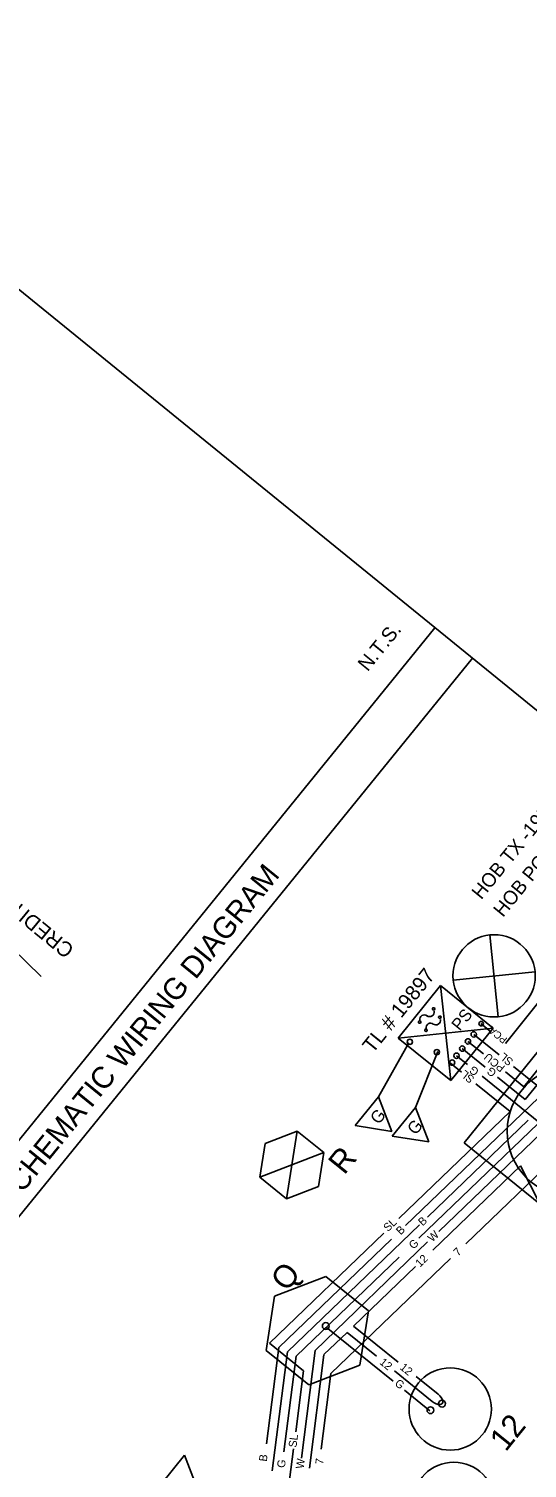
# Model space of a CAD drawing. Extents: x 592613 to 600223, y 4837996 to 4840103.
# Drawn here: x 592974.5 to 592995.2, y 4839219.9 to 4839279.7 of the extents above; entities that cross this region are included whole.
import ezdxf

# ---------------------------------------------------------------- set-up
doc = ezdxf.new("R2010")
doc.units = 0
for name, color, linetype in [('ENG_BORDER', 7, 'Continuous'), ('ENG_TITLEBLOCK', 7, 'Continuous'), ('ENG_TX_TITLEBLOCK', 7, 'Continuous'), ('Level 32', 7, 'Continuous'), ('Level 57', 7, 'Continuous'), ('ROW_ENG_ROW', 7, 'Continuous'), ('TCS_ELEC-CHAMBER-NEW', 7, 'Continuous'), ('TCS_FUSE', 7, 'Continuous'), ('TCS_HYDROSUPPLY', 7, 'Continuous'), ('TCS_PLATE', 7, 'Continuous'), ('TCS_POLE-EXIST', 7, 'Continuous'), ('TCS_POLE-NEW', 7, 'Continuous'), ('TCS_POWER', 7, 'Continuous'), ('TCS_WR_12', 7, 'Continuous'), ('TCS_WR_7', 7, 'Continuous'), ('TCS_WR_B', 7, 'Continuous'), ('TCS_WR_G', 7, 'Continuous'), ('TCS_WR_PCA', 7, 'Continuous'), ('TCS_WR_PCU', 7, 'Continuous'), ('TCS_WR_SL', 7, 'Continuous'), ('TCS_WR_W', 7, 'Continuous')]:
    doc.layers.add(name, color=color, linetype=linetype)

msp = doc.modelspace()

# ---------------------------------------------------------------- linework, layer by layer
at = {"layer": 'ENG_BORDER'}
msp.add_line((593034.225, 4839220.017), (592929.842, 4839304.827), dxfattribs=at)
at = {"layer": 'ENG_TITLEBLOCK'}
for p, q in [((592963.831, 4839220.942), (592991.37, 4839254.837)), ((592965.387, 4839219.678), (592992.927, 4839253.572))]:
    msp.add_line(p, q, dxfattribs=at)
at = {"layer": 'Level 57'}
msp.add_circle((592993.289, 4839238.384), 0.095, dxfattribs=at)
at = {"layer": 'ROW_ENG_ROW'}
msp.add_line((592974.997, 4839240.339), (592971.811, 4839243.434), dxfattribs=at)
at = {"layer": 'TCS_ELEC-CHAMBER-NEW'}
for p, q in [((592996.605, 4839238.421), (592992.576, 4839233.433)), ((592984.315, 4839233.409), (592985.645, 4839233.921)), ((592985.645, 4839233.921), (592985.203, 4839231.106)), ((592985.645, 4839233.921), (592986.753, 4839233.026)), ((592984.094, 4839232.001), (592984.315, 4839233.409)), ((592992.576, 4839233.433), (592997.564, 4839229.404)), ((592984.094, 4839232.001), (592986.753, 4839233.026)), ((592986.753, 4839233.026), (592986.532, 4839231.618)), ((592985.203, 4839231.106), (592984.094, 4839232.001)), ((592986.532, 4839231.618), (592985.203, 4839231.106)), ((592984.702, 4839227.06), (592986.829, 4839227.88)), ((592986.829, 4839227.88), (592988.603, 4839226.448)), ((592984.348, 4839224.808), (592984.702, 4839227.06)), ((592988.603, 4839226.448), (592988.249, 4839224.195)), ((592986.122, 4839223.375), (592984.348, 4839224.808)), ((592988.249, 4839224.195), (592986.122, 4839223.375))]:
    msp.add_line(p, q, dxfattribs=at)
msp.add_circle((592997.085, 4839233.914), 2.715, dxfattribs=at)
at = {"layer": 'TCS_FUSE'}
for centre, radius, start, end in [((592990.926, 4839238.562), 0.189, 53.79169, 190.44043), ((592991.149, 4839238.866), 0.189, 233.79169, 10.44043), ((592991.311, 4839238.998), 0.0513, 51.07435, 231.07435), ((592991.311, 4839238.998), 0.0513, 231.07435, 51.07435), ((592991.408, 4839238.524), 0.189, 233.79169, 10.44043), ((592991.57, 4839238.655), 0.0513, 51.07435, 231.07435), ((592991.57, 4839238.655), 0.0513, 231.07435, 51.07435), ((592990.735, 4839238.451), 0.0513, 51.07435, 231.07435), ((592990.735, 4839238.451), 0.0513, 231.07435, 51.07435), ((592990.994, 4839238.109), 0.0513, 51.07435, 231.07435), ((592990.994, 4839238.109), 0.0513, 231.07435, 51.07435), ((592991.185, 4839238.219), 0.189, 53.79169, 190.44043)]:
    msp.add_arc(centre, radius, start, end, dxfattribs=at)
at = {"layer": 'TCS_PLATE'}
for p, q in [((592989.015, 4839235.345), (592988.048, 4839234.148)), ((592989.569, 4839233.909), (592989.015, 4839235.345)), ((592990.556, 4839234.905), (592989.589, 4839233.709)), ((592991.109, 4839233.47), (592990.556, 4839234.905)), ((592988.048, 4839234.148), (592989.569, 4839233.909)), ((592989.589, 4839233.709), (592991.109, 4839233.47)), ((592980.957, 4839220.448), (592979.99, 4839219.252)), ((592981.511, 4839219.013), (592980.957, 4839220.448))]:
    msp.add_line(p, q, dxfattribs=at)
at = {"layer": 'TCS_POLE-EXIST'}
for p, q in [((592994.001, 4839238.672), (592993.656, 4839242.074)), ((592995.529, 4839240.546), (592992.127, 4839240.2))]:
    msp.add_line(p, q, dxfattribs=at)
msp.add_circle((592993.828, 4839240.374), 1.71, dxfattribs=at)
at = {"layer": 'TCS_POLE-NEW'}
for centre in [(592992.003, 4839222.372), (592992.152, 4839218.453)]:
    msp.add_circle(centre, 1.71, dxfattribs=at)
at = {"layer": 'TCS_POWER'}
for p, q in [((592991.604, 4839239.965), (592989.841, 4839237.784)), ((592992.022, 4839236.021), (592991.604, 4839239.965)), ((592993.785, 4839238.202), (592991.604, 4839239.965)), ((592989.841, 4839237.784), (592993.785, 4839238.202)), ((592992.022, 4839236.021), (592993.785, 4839238.202)), ((592989.841, 4839237.784), (592992.022, 4839236.021))]:
    msp.add_line(p, q, dxfattribs=at)
at = {"layer": 'TCS_WR_12'}
for p, q in [((592994.926, 4839232.484), (592991.275, 4839228.976)), ((592996.111, 4839230.135), (592994.926, 4839232.484)), ((592990.563, 4839228.292), (592987.986, 4839225.815)), ((592987.713, 4839225.553), (592986.755, 4839224.632)), ((592987.713, 4839225.553), (592988.938, 4839224.563)), ((592987.989, 4839225.818), (592989.845, 4839224.319)), ((592986.754, 4839224.625), (592986.154, 4839219.919)), ((592989.687, 4839223.958), (592991.257, 4839222.69)), ((592990.587, 4839223.72), (592991.496, 4839222.987))]:
    msp.add_line(p, q, dxfattribs=at)
msp.add_ellipse((592991.377, 4839222.839), major_axis=(-0.296, 0.239), ratio=0.5, start_param=1.570796, end_param=4.712389, dxfattribs=at)
at = {"layer": 'TCS_WR_7'}
for p, q in [((592996.76, 4839233.187), (592992.648, 4839229.235)), ((592992.013, 4839228.625), (592987.037, 4839223.844)), ((592987.037, 4839223.844), (592986.637, 4839220.702))]:
    msp.add_line(p, q, dxfattribs=at)
at = {"layer": 'TCS_WR_B'}
for p, q in [((592995.666, 4839235.298), (592990.147, 4839229.994)), ((592995.25, 4839234.373), (592991.061, 4839230.345)), ((592990.731, 4839230.028), (592985.237, 4839224.749)), ((592989.558, 4839229.428), (592984.877, 4839224.93)), ((592984.877, 4839224.93), (592984.367, 4839220.927)), ((592985.237, 4839224.749), (592984.608, 4839219.808))]:
    msp.add_line(p, q, dxfattribs=at)
at = {"layer": 'TCS_WR_G'}
for p, q in [((592995.125, 4839235.232), (592997.888, 4839238.653)), ((592989.015, 4839235.345), (592990.282, 4839237.594)), ((592993.451, 4839236.584), (592992.502, 4839237.351)), ((592991.485, 4839237.225), (592990.562, 4839234.9)), ((592992.726, 4839236.682), (592992.263, 4839237.055)), ((592995.687, 4839234.29), (592993.325, 4839236.198)), ((592995.125, 4839235.232), (592993.967, 4839236.167)), ((592995.662, 4839234.243), (592990.696, 4839229.467)), ((592989.886, 4839228.688), (592985.597, 4839224.563)), ((592986.851, 4839225.77), (592989.632, 4839223.524)), ((592985.597, 4839224.563), (592985.091, 4839220.595)), ((592990.101, 4839223.151), (592991.15, 4839222.298))]:
    msp.add_line(p, q, dxfattribs=at)
at = {"layer": 'TCS_WR_PCA'}
for p, q in [((592994.298, 4839237.565), (592995.859, 4839239.497)), ((592993.696, 4839238.052), (592993.281, 4839238.387))]:
    msp.add_line(p, q, dxfattribs=at)
at = {"layer": 'TCS_WR_PCU'}
for p, q in [((592995.068, 4839235.767), (592997.337, 4839238.576)), ((592993.381, 4839237.129), (592992.741, 4839237.647)), ((592995.068, 4839235.767), (592994.304, 4839236.384))]:
    msp.add_line(p, q, dxfattribs=at)
at = {"layer": 'TCS_WR_SL'}
for p, q in [((592994.041, 4839237.085), (592992.979, 4839237.942)), ((592992.474, 4839236.37), (592992.012, 4839236.744)), ((592996.489, 4839235.107), (592994.637, 4839236.603)), ((592994.501, 4839234.733), (592993.073, 4839235.887)), ((592994.501, 4839234.733), (592989.87, 4839230.283)), ((592989.244, 4839229.681), (592984.486, 4839225.109)), ((592984.486, 4839225.109), (592985.903, 4839223.964)), ((592985.903, 4839223.964), (592985.58, 4839221.424)), ((592985.49, 4839220.722), (592985.11, 4839217.734))]:
    msp.add_line(p, q, dxfattribs=at)
at = {"layer": 'TCS_WR_W'}
for p, q in [((592996.508, 4839234.525), (592991.532, 4839229.744)), ((592991.065, 4839229.318), (592986.394, 4839224.806)), ((592986.394, 4839224.806), (592985.822, 4839220.326))]:
    msp.add_line(p, q, dxfattribs=at)
for centre, radius in [((592992.979, 4839237.942), 0.111), ((592990.325, 4839237.631), 0.111), ((592992.502, 4839237.351), 0.111), ((592992.741, 4839237.647), 0.111), ((592991.447, 4839237.2), 0.111), ((592992.085, 4839236.767), 0.111), ((592992.263, 4839237.055), 0.111), ((592986.829, 4839225.819), 0.142), ((592991.182, 4839222.324), 0.142), ((592991.664, 4839222.595), 0.142)]:
    msp.add_circle(centre, radius, dxfattribs=at)

# ---------------------------------------------------------------- texts
at = {"layer": 'ENG_TX_TITLEBLOCK'}
for s, height, p in [('N.T.S.', 0.6, (592988.573, 4839252.987)), ('SCHEMATIC WIRING DIAGRAM', 0.9, (592973.698, 4839230.689))]:
    msp.add_text(s, height=height, rotation=50.9062, dxfattribs=at).set_placement(p)
at = {"layer": 'Level 32'}
msp.add_text('CREDITVIEW ROAD', height=0.625, rotation=140.5921, dxfattribs=at).set_placement((592976.415, 4839241.537))
at = {"layer": 'TCS_ELEC-CHAMBER-NEW'}
for s, p in [('R', (592987.598, 4839232.068)), ('Q', (592985.207, 4839227.211))]:
    msp.add_text(s, height=0.95, rotation=51.07435, dxfattribs=at).set_placement(p)
at = {"layer": 'TCS_HYDROSUPPLY'}
for s, p in [('HOB TX -19897', (592993.294, 4839243.509)), ('HOB POLE #11347', (592994.196, 4839242.776))]:
    msp.add_text(s, height=0.5814, rotation=50.88098, dxfattribs=at).set_placement(p)
at = {"layer": 'TCS_PLATE'}
for p in [(592989.027, 4839234.166), (592990.567, 4839233.726)]:
    msp.add_text('G', height=0.513, rotation=51.07435, dxfattribs=at).set_placement(p)
at = {"layer": 'TCS_POLE-NEW'}
msp.add_text('12', height=0.95, rotation=51.07435, dxfattribs=at).set_placement((592994.31, 4839220.564))
at = {"layer": 'TCS_POWER'}
for s, height, rotation, p in [('TL # 19897', 0.6175, 51.07435, (592988.783, 4839237.12)), ('PS', 0.4986, 51.00911, (592992.398, 4839238.056))]:
    msp.add_text(s, height=height, rotation=rotation, dxfattribs=at).set_placement(p)
at = {"layer": 'TCS_WR_12'}
for rotation, p in [(43.85968, (592990.746, 4839228.246)), (321.07435, (592989.039, 4839224.269)), (321.07435, (592989.883, 4839224.052))]:
    msp.add_text('12', height=0.3325, rotation=rotation, dxfattribs=at).set_placement(p)
at = {"layer": 'TCS_WR_7'}
for height, rotation, p in [(0.333, 43.85968, (592992.33, 4839228.7)), (0.332, 82.74263, (592986.721, 4839220.055))]:
    msp.add_text('7', height=height, rotation=rotation, dxfattribs=at).set_placement(p)
at = {"layer": 'TCS_WR_B'}
for height, rotation, p in [(0.333, 43.85968, (592990.86, 4839229.958)), (0.333, 43.85968, (592989.942, 4839229.585)), (0.332, 82.74263, (592984.376, 4839220.175))]:
    msp.add_text('B', height=height, rotation=rotation, dxfattribs=at).set_placement(p)
at = {"layer": 'TCS_WR_G'}
for height, rotation, p in [(0.333, 141.07435, (592993.229, 4839236.442)), (0.333, 141.07435, (592993.959, 4839236.398)), (0.332, 43.85968, (592990.473, 4839228.991)), (0.333, 321.07435, (592989.667, 4839223.388)), (0.332, 82.74263, (592985.127, 4839219.912))]:
    msp.add_text('G', height=height, rotation=rotation, dxfattribs=at).set_placement(p)
at = {"layer": 'TCS_WR_PCA'}
msp.add_text('PCA', height=0.2993, rotation=141.05743, dxfattribs=at).set_placement((592994.397, 4839237.767))
at = {"layer": 'TCS_WR_PCU'}
msp.add_text('PCU', height=0.3325, rotation=141.07435, dxfattribs=at).set_placement((592994.309, 4839236.604))
at = {"layer": 'TCS_WR_SL'}
for rotation, p in [(141.07435, (592994.652, 4839236.861)), (141.07435, (592993.039, 4839236.136)), (43.85968, (592989.415, 4839229.722)), (82.74263, (592985.609, 4839220.759))]:
    msp.add_text('SL', height=0.3325, rotation=rotation, dxfattribs=at).set_placement(p)
at = {"layer": 'TCS_WR_W'}
for height, rotation, p in [(0.333, 43.85968, (592991.26, 4839229.291)), (0.332, 82.74263, (592985.907, 4839219.875))]:
    msp.add_text('W', height=height, rotation=rotation, dxfattribs=at).set_placement(p)

doc.saveas('drawing.dxf')
